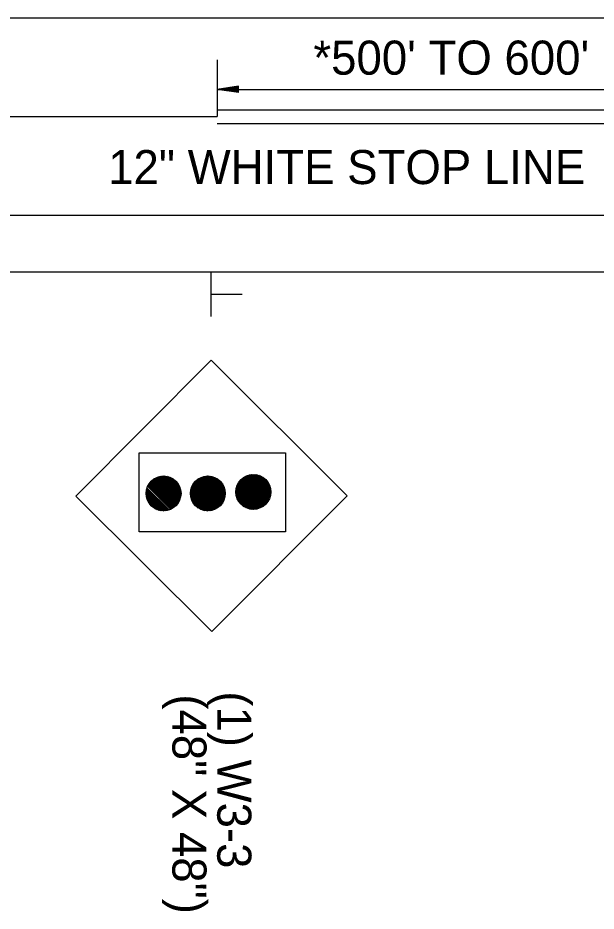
# Model space of a CAD drawing. Extents: x 1806907 to 1812607, y 675071 to 676228.
# Drawn here: x 1809628.7 to 1809730.5, y 675638.5 to 675795.9 of the extents above; entities that cross this region are included whole.
import ezdxf

# ---------------------------------------------------------------- set-up
doc = ezdxf.new("R2010")
doc.units = 0
doc.layers.add('Default', color=7, linetype='Continuous')

msp = doc.modelspace()

# ---------------------------------------------------------------- linework, layer by layer
at = {"layer": 'Default'}
for p, q in [((1809227.51, 675795.87), (1809776.27, 675795.87)), ((1809663.82, 675788.48), (1809663.82, 675778.48)), ((1809667.57, 675783.81), (1809663.82, 675783.25)), ((1809667.57, 675783.72), (1809664.45, 675783.25)), ((1809667.57, 675782.69), (1809667.57, 675783.81)), ((1809667.57, 675782.69), (1809663.82, 675783.25)), ((1809663.82, 675783.25), (1809761.42, 675783.25)), ((1809667.57, 675782.78), (1809664.45, 675783.25)), ((1809667.57, 675783.63), (1809665.1, 675783.25)), ((1809667.57, 675782.88), (1809665.1, 675783.25)), ((1809667.57, 675783.53), (1809665.72, 675783.25)), ((1809667.57, 675782.97), (1809665.72, 675783.25)), ((1809667.57, 675783.44), (1809666.36, 675783.25)), ((1809667.57, 675783.07), (1809666.36, 675783.25)), ((1809667.57, 675783.34), (1809666.98, 675783.25)), ((1809667.57, 675783.16), (1809666.98, 675783.25)), ((1809663.82, 675779.68), (1809761.42, 675779.68)), ((1809227.51, 675778.48), (1809663.82, 675778.48)), ((1809663.82, 675777.28), (1809761.42, 675777.28)), ((1809227.51, 675761.1), (1809776.27, 675761.1)), ((1809227.51, 675751.1), (1810285.86, 675751.1)), ((1809662.75, 675743.28), (1809662.75, 675751.1)), ((1809662.86, 675747.17), (1809668.2, 675747.17)), ((1809638.89, 675711.59), (1809662.75, 675735.54)), ((1809686.67, 675711.67), (1809662.75, 675735.54)), ((1809652.37, 675714.43), (1809656.72, 675710.09)), ((1809652.48, 675714.52), (1809656.8, 675710.2)), ((1809652.59, 675714.6), (1809656.88, 675710.3)), ((1809652.7, 675714.67), (1809656.96, 675710.42)), ((1809652.82, 675714.75), (1809657.03, 675710.54)), ((1809652.94, 675714.81), (1809657.1, 675710.66)), ((1809653.07, 675714.87), (1809657.16, 675710.79)), ((1809653.2, 675714.93), (1809657.21, 675710.92)), ((1809653.34, 675714.98), (1809657.27, 675711.06)), ((1809653.49, 675715.03), (1809657.31, 675711.2)), ((1809653.64, 675715.07), (1809657.35, 675711.35)), ((1809653.79, 675715.1), (1809657.38, 675711.51)), ((1809653.96, 675715.13), (1809657.41, 675711.67)), ((1809654.13, 675715.14), (1809657.43, 675711.85)), ((1809654.31, 675715.15), (1809657.43, 675712.03)), ((1809654.5, 675715.15), (1809657.43, 675712.22)), ((1809654.71, 675715.13), (1809657.41, 675712.43)), ((1809654.94, 675715.1), (1809657.38, 675712.65)), ((1809655.18, 675715.04), (1809657.32, 675712.9)), ((1809655.47, 675714.94), (1809657.23, 675713.19)), ((1809655.82, 675714.78), (1809657.06, 675713.54)), ((1809660.12, 675714.39), (1809664.47, 675710.03)), ((1809660.22, 675714.47), (1809664.56, 675710.14)), ((1809660.33, 675714.56), (1809664.64, 675710.24)), ((1809660.44, 675714.63), (1809664.72, 675710.35)), ((1809660.55, 675714.71), (1809664.79, 675710.47)), ((1809660.67, 675714.78), (1809664.86, 675710.59)), ((1809660.8, 675714.84), (1809664.92, 675710.72)), ((1809660.93, 675714.9), (1809664.98, 675710.85)), ((1809661.07, 675714.95), (1809665.04, 675710.98)), ((1809661.21, 675715), (1809665.09, 675711.12)), ((1809661.35, 675715.05), (1809665.13, 675711.27)), ((1809661.51, 675715.08), (1809665.17, 675711.42)), ((1809661.67, 675715.11), (1809665.2, 675711.58)), ((1809661.83, 675715.14), (1809665.22, 675711.75)), ((1809662.01, 675715.15), (1809665.23, 675711.93)), ((1809662.2, 675715.15), (1809665.24, 675712.11)), ((1809662.39, 675715.14), (1809665.23, 675712.31)), ((1809662.61, 675715.12), (1809665.2, 675712.53)), ((1809662.84, 675715.07), (1809665.16, 675712.76)), ((1809663.11, 675715), (1809665.08, 675713.02)), ((1809663.41, 675714.88), (1809664.97, 675713.33)), ((1809663.83, 675714.65), (1809664.74, 675713.75)), ((1809667.86, 675714.38), (1809672.22, 675710.03)), ((1809667.95, 675714.48), (1809672.32, 675710.12)), ((1809668.05, 675714.58), (1809672.41, 675710.22)), ((1809668.15, 675714.67), (1809672.5, 675710.32)), ((1809668.25, 675714.76), (1809672.59, 675710.42)), ((1809668.36, 675714.84), (1809672.67, 675710.53)), ((1809668.47, 675714.92), (1809672.75, 675710.64)), ((1809668.59, 675714.99), (1809672.82, 675710.75)), ((1809668.71, 675715.06), (1809672.89, 675710.87)), ((1809668.83, 675715.12), (1809672.96, 675711)), ((1809668.96, 675715.18), (1809673.02, 675711.13)), ((1809669.1, 675715.24), (1809673.07, 675711.26)), ((1809669.24, 675715.29), (1809673.12, 675711.4)), ((1809669.38, 675715.33), (1809673.16, 675711.55)), ((1809669.54, 675715.37), (1809673.2, 675711.7)), ((1809669.7, 675715.4), (1809673.23, 675711.86)), ((1809669.86, 675715.42), (1809673.25, 675712.03)), ((1809670.04, 675715.43), (1809673.26, 675712.21)), ((1809670.23, 675715.43), (1809673.27, 675712.39)), ((1809670.43, 675715.43), (1809673.26, 675712.59)), ((1809670.64, 675715.4), (1809673.23, 675712.81)), ((1809670.88, 675715.36), (1809673.19, 675713.04)), ((1809671.14, 675715.28), (1809673.12, 675713.3)), ((1809671.45, 675715.16), (1809673, 675713.61)), ((1809671.86, 675714.94), (1809672.77, 675714.03)), ((1809651.39, 675712.95), (1809655.23, 675709.11)), ((1809651.44, 675713.09), (1809655.37, 675709.16)), ((1809651.55, 675713.36), (1809655.64, 675709.27)), ((1809651.61, 675713.49), (1809655.77, 675709.33)), ((1809651.68, 675713.61), (1809655.89, 675709.4)), ((1809651.75, 675713.73), (1809656.01, 675709.47)), ((1809651.83, 675713.84), (1809656.12, 675709.54)), ((1809651.91, 675713.95), (1809656.23, 675709.62)), ((1809651.99, 675714.06), (1809656.34, 675709.71)), ((1809652.08, 675714.16), (1809656.44, 675709.8)), ((1809652.17, 675714.25), (1809656.54, 675709.89)), ((1809652.27, 675714.35), (1809656.63, 675709.99)), ((1809659.17, 675712.87), (1809662.95, 675709.09)), ((1809659.21, 675713.01), (1809663.1, 675709.13)), ((1809659.26, 675713.15), (1809663.24, 675709.18)), ((1809659.32, 675713.29), (1809663.37, 675709.23)), ((1809659.38, 675713.42), (1809663.5, 675709.29)), ((1809659.44, 675713.54), (1809663.63, 675709.36)), ((1809659.51, 675713.66), (1809663.75, 675709.43)), ((1809659.59, 675713.78), (1809663.86, 675709.5)), ((1809659.66, 675713.89), (1809663.97, 675709.58)), ((1809659.75, 675714), (1809664.08, 675709.66)), ((1809659.83, 675714.1), (1809664.19, 675709.75)), ((1809659.92, 675714.2), (1809664.28, 675709.84)), ((1809660.02, 675714.3), (1809664.38, 675709.93)), ((1809667.14, 675712.83), (1809670.67, 675709.3)), ((1809667.17, 675712.99), (1809670.83, 675709.33)), ((1809667.2, 675713.15), (1809670.98, 675709.37)), ((1809667.25, 675713.29), (1809671.13, 675709.41)), ((1809667.3, 675713.43), (1809671.27, 675709.46)), ((1809667.35, 675713.57), (1809671.4, 675709.52)), ((1809667.41, 675713.7), (1809671.53, 675709.58)), ((1809667.47, 675713.83), (1809671.66, 675709.64)), ((1809667.54, 675713.95), (1809671.78, 675709.71)), ((1809667.62, 675714.06), (1809671.9, 675709.78)), ((1809667.7, 675714.17), (1809672.01, 675709.86)), ((1809667.78, 675714.28), (1809672.11, 675709.94)), ((1809662.83, 675687.73), (1809638.89, 675711.59)), ((1809651.27, 675712.31), (1809654.59, 675708.99)), ((1809651.27, 675712.13), (1809654.41, 675708.98)), ((1809651.27, 675711.93), (1809654.22, 675708.99)), ((1809651.28, 675711.73), (1809654.01, 675709)), ((1809651.29, 675712.48), (1809654.76, 675709.01)), ((1809651.32, 675712.64), (1809654.93, 675709.04)), ((1809651.32, 675711.51), (1809653.79, 675709.03)), ((1809651.35, 675712.8), (1809655.08, 675709.07)), ((1809651.37, 675711.26), (1809653.54, 675709.09)), ((1809659.07, 675712.21), (1809662.29, 675708.99)), ((1809659.07, 675712.02), (1809662.11, 675708.98)), ((1809659.08, 675712.38), (1809662.47, 675709)), ((1809659.08, 675711.82), (1809661.91, 675708.99)), ((1809659.1, 675712.55), (1809662.64, 675709.02)), ((1809659.1, 675711.61), (1809661.69, 675709.02)), ((1809659.13, 675712.71), (1809662.8, 675709.05)), ((1809659.15, 675711.37), (1809661.46, 675709.06)), ((1809662.83, 675687.73), (1809686.67, 675711.67)), ((1809667.1, 675712.49), (1809670.32, 675709.27)), ((1809667.1, 675712.3), (1809670.14, 675709.27)), ((1809667.11, 675712.67), (1809670.5, 675709.28)), ((1809667.11, 675712.1), (1809669.94, 675709.27)), ((1809667.13, 675711.89), (1809669.72, 675709.3)), ((1809667.18, 675711.66), (1809669.49, 675709.34)), ((1809667.25, 675711.39), (1809669.23, 675709.42)), ((1809651.46, 675710.98), (1809653.26, 675709.18)), ((1809651.62, 675710.64), (1809652.92, 675709.33)), ((1809652.03, 675710.04), (1809652.32, 675709.75)), ((1809659.22, 675711.11), (1809661.19, 675709.13)), ((1809659.34, 675710.8), (1809660.89, 675709.25)), ((1809659.57, 675710.38), (1809660.47, 675709.48)), ((1809667.37, 675711.08), (1809668.92, 675709.54)), ((1809667.6, 675710.67), (1809668.5, 675709.77))]:
    msp.add_line(p, q, dxfattribs=at)
msp.add_lwpolyline([(1809675.8, 675719.25), (1809675.8, 675705.31), (1809650.07, 675705.31), (1809650.07, 675719.25)], close=True, dxfattribs=at)
for centre in [(1809654.35, 675712.07), (1809662.15, 675712.07), (1809670.18, 675712.35)]:
    msp.add_circle(centre, 3.08, dxfattribs=at)

# ---------------------------------------------------------------- texts
for s, p in [("*500' TO 600'", (1809680.73, 675785.86)), ('12" WHITE STOP LINE', (1809644.6, 675766.58))]:
    msp.add_text(s, height=6, dxfattribs=at).set_placement(p)
for s, p in [('(1) W3-3', (1809663.81, 675677.21)), ('(48" X 48")', (1809655.91, 675676.68))]:
    msp.add_text(s, height=6, rotation=270, dxfattribs=at).set_placement(p)

doc.saveas('drawing.dxf')
